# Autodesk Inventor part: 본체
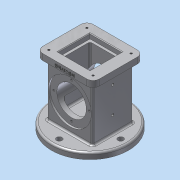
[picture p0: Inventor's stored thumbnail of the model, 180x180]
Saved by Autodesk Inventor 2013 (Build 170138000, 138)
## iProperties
Created: 2018-10
Part Number: 본체
Material: 알루미늄 6061
Document SubType Name: Modeling
Designer: dgall
Density: 2.71 g/cm^3
Mass: 988.475 g
Surface Area: 751.7 cm^2
Volume: 364.751 cm^3
Author: dgall
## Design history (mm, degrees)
sketch "스케치1"
  geometry: L1 (-37, 33)-(37, 33); L2 (37, 33)-(37, -33); L3 (37, -33)-(-37, -33); L4 (-37, -33)-(-37, 33); 3 further points
  constraints: 8 end point, 2 midpoint, 2 parallel, 1 horizontal, 1 horizontal alignment, 1 perpendicular, 1 vertical alignment
  dimensions: "d0" = 74 distance of L1.start L1.end; "d2" = 66 distance of L1.end L2.end
extrude "돌출1" new body sketch "스케치1" stored distance "d3" = 88; taper "d4" = 0 deg
sketch "스케치2"
  geometry: L1 (-46, 41)-(46, 41); L2 (46, 41)-(46, -41); L3 (46, -41)-(-46, -41); L4 (-46, -41)-(-46, 41); 3 further points
  constraints: 8 end point, 2 midpoint, 2 parallel, 1 horizontal, 1 horizontal alignment, 1 perpendicular, 1 vertical alignment
  dimensions: "d5" = 82 distance of L1.end L2.end; "d7" = 92 distance of L1.start L1.end
extrude "돌출2" join sketch "스케치2" distance "d8" = 10; taper "d9" = 0 deg
sketch "스케치3"
  geometry: L1 (-26, 26)-(26, 26); L2 (26, 26)-(26, -26); L3 (26, -26)-(-26, -26); L4 (-26, -26)-(-26, 26); 3 further points
  constraints: 8 end point, 2 midpoint, 2 parallel, 2 perpendicular, 1 horizontal, 1 horizontal alignment, 1 vertical alignment
  dimensions: "d10" = 52 distance of L1.start L1.end
extrude "돌출3" cut sketch "스케치3" distance "d12" = 8; taper "d13" = 0 deg
sketch "스케치4"
  geometry: L1 (-22, 22)-(22, 22); L2 (22, 22)-(22, -22); L3 (22, -22)-(-22, -22); L4 (-22, -22)-(-22, 22); 3 further points
  constraints: 8 end point, 2 midpoint, 2 parallel, 2 perpendicular, 1 horizontal, 1 horizontal alignment, 1 vertical alignment
  dimensions: "d14" = 44 distance of L1.start L1.end
extrude "돌출4" cut sketch "스케치4" distance "d16" = 74; taper "d17" = 0 deg
fillet "모깎기2" dims "d80" = 3
fillet "모깎기3" dims "d81" = 3
node "작업 평면1"
sketch "스케치5"
  geometry: C1 r 62.5 at (0, 0); 1 further point
  constraints: 1 centre point, 1 coincident
  dimensions: "d19" = 125 diameter of C1
extrude "돌출5" join sketch "스케치5" distance "d21" = 10; taper "d22" = 0 deg
sketch "스케치6" dims "d23" = 100
  geometry: C1 r 62.5 at (0, 0) reference; 2 further points
  constraints: 2 vertical alignment, 1 coincident, 2 other
hole "구멍1" sketch "스케치6" at (0, 50) diameter "d25" = 9; stored, may be unused: countersink angle "d29" = 90 deg, drill point angle "d31" = 118 deg; dims "d26" = 6, "d27" = 4, "d28" = 2, "d30" = 8
sketch "스케치7"
  geometry: C1 r 35 at (37, -44); 1 further point
  constraints: 1 centre point, 1 coincident
  dimensions: "d35" = 70 diameter of C1
extrude "돌출6" cut sketch "스케치7" distance "d37" = 3; taper "d38" = 0 deg
hole "구멍2" diameter "d41" = 48; stored, may be unused: countersink angle "d45" = 90 deg, drill point angle "d47" = 118 deg; dims "d39" = 10, "d40" = 10, "d42" = 6, "d43" = 4, "d44" = 2, "d46" = 8
sketch "스케치8" dims "d48" = 58
  geometry: C1 r 24 at (0, 0) reference; C2 r 35 at (0, 0) reference; 2 further points
  constraints: 2 vertical alignment, 1 coincident, 2 other
hole "구멍3" sketch "스케치8" at (0, -29) diameter "d50" = 3.242; stored, may be unused: countersink angle "d54" = 82 deg, drill point angle "d56" = 118 deg; dims "d51" = 4, "d52" = 3.023, "d53" = 2, "d55" = 6
fillet "모깎기1" dims "d60" = 10
hole "구멍4" diameter "d63" = 3.242; stored, may be unused: countersink angle "d67" = 82 deg, drill point angle "d69" = 118 deg; dims "d61" = 10, "d62" = 10, "d64" = 4, "d65" = 3.023, "d66" = 2, "d68" = 6
sketch "스케치9"
  geometry: L1 (98, -29.5)-(98, 95.5) reference; L2 (98, 37.5)-(98, 28.5) reference; L3 (98, 33)-(61, 33); L4 (61, 33)-(18, 33); 3 further points
  constraints: 4 end point, 2 coincident, 1 collinear, 1 midpoint, 1 perpendicular
  dimensions: "d70" = 37 distance of L3.start L3.end; "d72" = 43 distance of L3.end L4.end
hole "구멍5" sketch "스케치9" at (61, 33), (18, 33) diameter "d73" = 4.134; stored, may be unused: countersink angle "d77" = 82 deg, drill point angle "d79" = 118 deg; dims "d74" = 4, "d75" = 3.023, "d76" = 2, "d78" = 20
fillet "모깎기4" dims "d82" = 3
fillet "모깎기5" dims "d83" = 3
node "작업 평면2"
sketch "스케치10"
  geometry: L1 (-62.5, -54)-(62.5, -54) reference; L2 (-28, -54)-(-24.826, -36); L3 (-24.826, -36)-(0, -36); L4 (0, -36)-(0, -54); 1 further point
  constraints: 6 end point, 1 midpoint, 1 parallel, 1 point on line, 1 vertical alignment
  dimensions: "d85" = 18 distance between parallel lines of L1 L3; "d87" = 28 distance of L4.end L2.start; "d88" = 80 deg angle of L2 L1
revolve "회전1" sketch "스케치10" stored, may be unused: angle "d89" = 90 deg
fillet "모깎기6" dims "d90" = 3
chamfer "모따기1" distance "d91" = 1; stored, may be unused: second distance "d92" = 2, angle "d93" = 45 deg
sketch "스케치11"
  geometry: L1 (72, 0)-(0, 0) reference; L2 (-10, 10)-(-10, 0) reference; 2 further points
  constraints: 1 other
  dimensions: "d94" = 46 distance from line of L2 point (36, 4); "d95" = 4 distance from line of L1 point (36, 4)
feature "엠보싱1" sketch "스케치11" dims "d0" = 74, "d2" = 66, "d96" = 0.5, "d97" = 0
node "솔리드1"
pattern_circular "원형 패턴1" dims angle "d33" = 360 deg
mirror "대칭1"
pattern_circular "원형 패턴2" dims angle "d58" = 360 deg
mirror "대칭2"
mirror "대칭3"
mirror "대칭4"
other parameters: "d18" = -54, "d84" = 0
